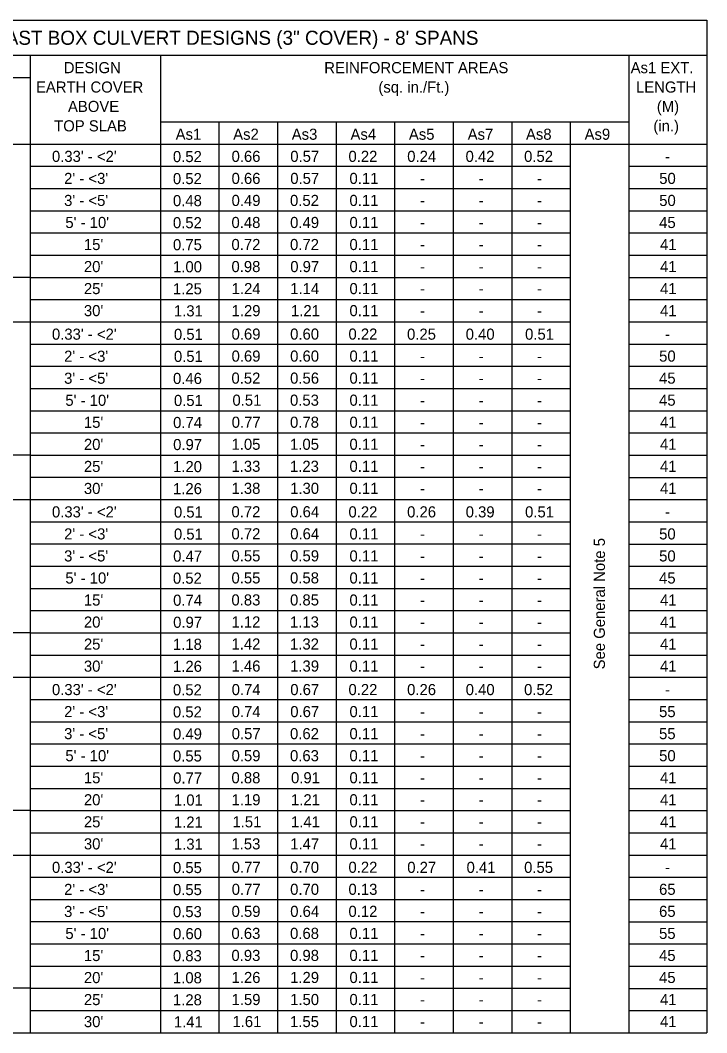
# Model space of a CAD drawing. Extents: x 10342.77 to 10344.98, y 76371.53 to 76372.62.
# Drawn here: x 10342.983 to 10343.372, y 76371.961 to 76372.535 of the extents above; entities that cross this region are included whole.
import ezdxf

# ---------------------------------------------------------------- set-up
doc = ezdxf.new("R2010")
doc.units = 0
doc.layers.add('AdhocPoint_dp', color=7, linetype='Continuous')
doc.layers.add('PlotBorder_dp', color=7, linetype='Continuous')

msp = doc.modelspace()

# ---------------------------------------------------------------- linework, layer by layer
at = {"layer": 'PlotBorder_dp'}
for p, q in [((10342.7771, 76372.53475), (10343.37184, 76372.53475)), ((10343.37184, 76372.53475), (10343.37184, 76371.96053)), ((10342.7771, 76372.51488), (10343.37184, 76372.51488)), ((10342.98818, 76372.51488), (10342.98818, 76371.96053)), ((10343.06206, 76372.51488), (10343.06206, 76371.96053)), ((10343.32765, 76372.51488), (10343.32765, 76371.96053)), ((10342.84574, 76372.50228), (10342.98818, 76372.50228)), ((10343.06206, 76372.47713), (10343.32765, 76372.47713)), ((10343.09526, 76372.47713), (10343.09526, 76371.96053)), ((10343.12846, 76372.47713), (10343.12846, 76371.96053)), ((10343.16166, 76372.47713), (10343.16166, 76371.96053)), ((10343.19486, 76372.47713), (10343.19486, 76371.96053)), ((10343.22806, 76372.47713), (10343.22806, 76371.96053)), ((10343.22806, 76372.47713), (10343.22806, 76371.96053)), ((10343.26125, 76372.47713), (10343.26125, 76371.96053)), ((10343.29445, 76372.47713), (10343.29445, 76371.96053)), ((10342.7771, 76372.46453), (10343.37184, 76372.46453)), ((10342.98818, 76372.45193), (10343.29445, 76372.45193)), ((10343.32765, 76372.45191), (10343.37184, 76372.45191)), ((10342.98818, 76372.43933), (10343.29445, 76372.43933)), ((10343.32765, 76372.43931), (10343.37184, 76372.43931)), ((10342.98818, 76372.42673), (10343.29445, 76372.42673)), ((10343.32765, 76372.42671), (10343.37184, 76372.42671)), ((10342.98818, 76372.41413), (10343.29445, 76372.41413)), ((10343.32765, 76372.41411), (10343.37184, 76372.41411)), ((10342.98818, 76372.40153), (10343.29445, 76372.40153)), ((10343.32765, 76372.40151), (10343.37184, 76372.40151)), ((10342.98818, 76372.38893), (10342.84574, 76372.38893)), ((10342.98818, 76372.38893), (10343.29445, 76372.38893)), ((10343.32765, 76372.38891), (10343.37184, 76372.38891)), ((10342.98818, 76372.37633), (10343.29445, 76372.37633)), ((10343.32765, 76372.37631), (10343.37184, 76372.37631)), ((10342.7771, 76372.36373), (10343.29445, 76372.36373)), ((10342.98281, 76372.36373), (10343.29445, 76372.36373)), ((10342.9888, 76372.36371), (10343.06097, 76372.36371)), ((10342.9888, 76372.36371), (10343.06097, 76372.36371)), ((10343.32765, 76372.36371), (10343.37184, 76372.36371)), ((10343.32765, 76372.36371), (10343.37184, 76372.36371)), ((10342.98818, 76372.35113), (10343.29445, 76372.35113)), ((10343.32765, 76372.35111), (10343.37184, 76372.35111)), ((10342.98818, 76372.33853), (10343.29445, 76372.33853)), ((10343.32765, 76372.33851), (10343.37184, 76372.33851)), ((10342.98818, 76372.32593), (10343.29445, 76372.32593)), ((10343.32765, 76372.32591), (10343.37184, 76372.32591)), ((10342.98818, 76372.31333), (10343.29445, 76372.31333)), ((10343.32765, 76372.31331), (10343.37184, 76372.31331)), ((10342.98818, 76372.30073), (10343.29445, 76372.30073)), ((10343.32765, 76372.30071), (10343.37184, 76372.30071)), ((10342.98818, 76372.28813), (10342.84574, 76372.28813)), ((10342.98818, 76372.28813), (10343.29445, 76372.28813)), ((10343.32765, 76372.28811), (10343.37184, 76372.28811)), ((10342.98818, 76372.27553), (10343.29445, 76372.27553)), ((10343.32765, 76372.27551), (10343.37184, 76372.27551)), ((10342.7771, 76372.26293), (10343.29445, 76372.26293)), ((10342.98281, 76372.26293), (10343.29445, 76372.26293)), ((10342.9888, 76372.26291), (10343.06097, 76372.26291)), ((10342.9888, 76372.26291), (10343.06097, 76372.26291)), ((10342.9888, 76372.26291), (10343.06097, 76372.26291)), ((10343.32765, 76372.26291), (10343.37184, 76372.26291)), ((10343.32765, 76372.26291), (10343.37184, 76372.26291)), ((10342.98818, 76372.25033), (10343.29445, 76372.25033)), ((10343.32765, 76372.25031), (10343.37184, 76372.25031)), ((10342.98818, 76372.23773), (10343.29445, 76372.23773)), ((10343.32765, 76372.23771), (10343.37184, 76372.23771)), ((10342.98818, 76372.22513), (10343.29445, 76372.22513)), ((10343.32765, 76372.22511), (10343.37184, 76372.22511)), ((10342.98818, 76372.21253), (10343.29445, 76372.21253)), ((10343.32765, 76372.21251), (10343.37184, 76372.21251)), ((10342.98818, 76372.19993), (10343.29445, 76372.19993)), ((10343.32765, 76372.19991), (10343.37184, 76372.19991)), ((10342.98818, 76372.18733), (10342.84574, 76372.18733)), ((10342.98818, 76372.18733), (10343.29445, 76372.18733)), ((10343.32765, 76372.18731), (10343.37184, 76372.18731)), ((10342.98818, 76372.17473), (10343.29445, 76372.17473)), ((10343.32765, 76372.17471), (10343.37184, 76372.17471)), ((10342.7771, 76372.16213), (10343.29445, 76372.16213)), ((10342.9888, 76372.16211), (10343.06097, 76372.16211)), ((10343.32765, 76372.16211), (10343.37184, 76372.16211)), ((10342.98818, 76372.14953), (10343.29445, 76372.14953)), ((10343.32765, 76372.14951), (10343.37184, 76372.14951)), ((10342.98818, 76372.13693), (10343.29445, 76372.13693)), ((10343.32765, 76372.13691), (10343.37184, 76372.13691)), ((10342.98818, 76372.12433), (10343.29445, 76372.12433)), ((10343.32765, 76372.12431), (10343.37184, 76372.12431)), ((10342.98818, 76372.11173), (10343.29445, 76372.11173)), ((10343.32765, 76372.11171), (10343.37184, 76372.11171)), ((10342.98818, 76372.09913), (10343.29445, 76372.09913)), ((10343.32765, 76372.09911), (10343.37184, 76372.09911)), ((10342.98818, 76372.08653), (10342.84574, 76372.08653)), ((10342.98818, 76372.08653), (10343.29445, 76372.08653)), ((10343.32765, 76372.08651), (10343.37184, 76372.08651)), ((10342.98818, 76372.07393), (10343.29445, 76372.07393)), ((10343.32765, 76372.07391), (10343.37184, 76372.07391)), ((10342.7771, 76372.06133), (10343.29445, 76372.06133)), ((10342.9888, 76372.06131), (10343.06097, 76372.06131)), ((10343.32765, 76372.06131), (10343.37184, 76372.06131)), ((10342.98818, 76372.04873), (10343.29445, 76372.04873)), ((10343.32765, 76372.04871), (10343.37184, 76372.04871)), ((10342.98818, 76372.03613), (10343.29445, 76372.03613)), ((10343.32765, 76372.03611), (10343.37184, 76372.03611)), ((10342.98818, 76372.02353), (10343.29445, 76372.02353)), ((10343.32765, 76372.02351), (10343.37184, 76372.02351)), ((10342.98818, 76372.01093), (10343.29445, 76372.01093)), ((10343.32765, 76372.01091), (10343.37184, 76372.01091)), ((10342.98818, 76371.99833), (10343.29445, 76371.99833)), ((10343.32765, 76371.99831), (10343.37184, 76371.99831)), ((10342.98818, 76371.98573), (10342.84574, 76371.98573)), ((10342.98818, 76371.98573), (10343.29445, 76371.98573)), ((10343.32765, 76371.98571), (10343.37184, 76371.98571)), ((10342.98818, 76371.97313), (10343.29445, 76371.97313)), ((10342.9888, 76371.97311), (10343.06097, 76371.97311)), ((10343.32765, 76371.97311), (10343.37184, 76371.97311)), ((10342.7771, 76371.96053), (10343.37184, 76371.96053))]:
    msp.add_line(p, q, dxfattribs=at)

# ---------------------------------------------------------------- texts
at = {"layer": 'AdhocPoint_dp'}
for s, height, p in [('TABLE 12A - STANDARD PRECAST BOX CULVERT DESIGNS (3" COVER) - 8\' SPANS', 0.008, (10342.81744, 76372.52081)), ('As1', 0.0063, (10343.07068, 76372.46696)), ('As2', 0.0063, (10343.10331, 76372.46696)), ('As3', 0.0063, (10343.13651, 76372.46696)), ('As4', 0.0063, (10343.16984, 76372.46696)), ('As5', 0.0063, (10343.20294, 76372.46696)), ('As7', 0.0063, (10343.23628, 76372.46696)), ('As8', 0.0063, (10343.26933, 76372.46696)), ('As9', 0.0063, (10343.30257, 76372.46696))]:
    msp.add_text(s, height=height, dxfattribs=at).set_placement(p)
msp.add_text('See General Note 5', height=0.0063, rotation=90, dxfattribs=at).set_placement((10343.3141, 76372.16662))
at = {"layer": 'PlotBorder_dp'}
for s, p in [('DESIGN', (10343.00728, 76372.50472)), ('REINFORCEMENT AREAS', (10343.15496, 76372.50472)), ('EARTH COVER', (10342.99149, 76372.49372)), ('(sq. in./Ft.)', (10343.18566, 76372.49372)), ('ABOVE', (10343.00963, 76372.48272)), ('TOP SLAB', (10343.0018, 76372.47172)), ("0.33' - <2'", (10343.00054, 76372.45441)), ('0.52', (10343.06914, 76372.4543)), ('0.66', (10343.1024, 76372.45441)), ('0.57', (10343.13568, 76372.45441)), ('0.22', (10343.16869, 76372.45441)), ('0.24', (10343.202, 76372.45441)), ('0.42', (10343.23508, 76372.45441)), ('0.52', (10343.26827, 76372.45441)), ('-', (10343.34816, 76372.45441)), ("2' - <3'", (10343.00744, 76372.44191)), ('0.52', (10343.06914, 76372.4418)), ('0.66', (10343.1024, 76372.44191)), ('0.57', (10343.13568, 76372.44191)), ('0.11', (10343.16926, 76372.44191)), ('-', (10343.20928, 76372.44191)), ('-', (10343.24249, 76372.44191)), ('-', (10343.27567, 76372.44191)), ('50', (10343.3449, 76372.44191)), ("3' - <5'", (10343.00744, 76372.42941)), ('0.48', (10343.06916, 76372.4293)), ('0.49', (10343.1024, 76372.42941)), ('0.52', (10343.13554, 76372.42941)), ('0.11', (10343.16926, 76372.42941)), ('50', (10343.3449, 76372.42941)), ('-', (10343.20928, 76372.42941)), ('-', (10343.24249, 76372.42941)), ('-', (10343.27567, 76372.42941)), ("5' - 10'", (10343.00815, 76372.41691)), ('0.52', (10343.06914, 76372.4168)), ('0.48', (10343.10235, 76372.41691)), ('0.49', (10343.1356, 76372.41691)), ('0.11', (10343.16926, 76372.41691)), ('45', (10343.34485, 76372.41691)), ('-', (10343.20928, 76372.41691)), ('-', (10343.24249, 76372.41691)), ('-', (10343.27567, 76372.41691)), ("15'", (10343.01867, 76372.40441)), ('0.75', (10343.06916, 76372.4043)), ('0.72', (10343.10234, 76372.40441)), ('0.72', (10343.13554, 76372.40441)), ('0.11', (10343.16926, 76372.40441)), ('41', (10343.34539, 76372.40441)), ('-', (10343.20928, 76372.40441)), ('-', (10343.24249, 76372.40441)), ('-', (10343.27567, 76372.40441)), ("20'", (10343.01867, 76372.39191)), ('1.00', (10343.06922, 76372.3918)), ('0.98', (10343.10235, 76372.39191)), ('0.97', (10343.13568, 76372.39191)), ('0.11', (10343.16926, 76372.39191)), ('41', (10343.34539, 76372.39191)), ('-', (10343.20928, 76372.39191)), ('-', (10343.24249, 76372.39191)), ('-', (10343.27567, 76372.39191)), ("25'", (10343.01867, 76372.37941)), ('1.25', (10343.06916, 76372.3793)), ('1.24', (10343.10246, 76372.37941)), ('1.14', (10343.13566, 76372.37941)), ('0.11', (10343.16926, 76372.37941)), ('-', (10343.20928, 76372.37941)), ('-', (10343.24249, 76372.37941)), ('-', (10343.27567, 76372.37941)), ('41', (10343.34539, 76372.37941)), ("30'", (10343.01867, 76372.36691)), ('1.31', (10343.06971, 76372.3668)), ('1.29', (10343.1024, 76372.36691)), ('1.21', (10343.13611, 76372.36691)), ('0.11', (10343.16926, 76372.36691)), ('-', (10343.20928, 76372.36691)), ('-', (10343.24249, 76372.36691)), ('-', (10343.27567, 76372.36691)), ('41', (10343.34539, 76372.36691)), ("0.33' - <2'", (10343.00054, 76372.35357)), ('0.51', (10343.06971, 76372.35347)), ('0.69', (10343.1024, 76372.35363)), ('0.60', (10343.13562, 76372.35363)), ('0.22', (10343.16869, 76372.35363)), ('0.25', (10343.2019, 76372.35357)), ('0.40', (10343.23516, 76372.35357)), ('0.51', (10343.26883, 76372.35357)), ('-', (10343.34811, 76372.35363)), ("2' - <3'", (10343.00744, 76372.34107)), ('0.51', (10343.06971, 76372.34097)), ('0.69', (10343.1024, 76372.34113)), ('0.60', (10343.13562, 76372.34113)), ('0.11', (10343.16926, 76372.34113)), ('50', (10343.34485, 76372.34113)), ('-', (10343.20928, 76372.34107)), ('-', (10343.24249, 76372.34107)), ('-', (10343.27567, 76372.34107)), ("3' - <5'", (10343.00744, 76372.32857)), ('0.46', (10343.0692, 76372.32847)), ('0.52', (10343.10234, 76372.32863)), ('0.56', (10343.1356, 76372.32863)), ('0.11', (10343.16926, 76372.32863)), ('45', (10343.3448, 76372.32863)), ('-', (10343.20928, 76372.32857)), ('-', (10343.24249, 76372.32857)), ('-', (10343.27567, 76372.32857)), ("5' - 10'", (10343.00815, 76372.31607)), ('0.51', (10343.06971, 76372.31597)), ('0.51', (10343.1029, 76372.31613)), ('0.53', (10343.13553, 76372.31613)), ('0.11', (10343.16926, 76372.31613)), ('-', (10343.20928, 76372.31607)), ('-', (10343.24249, 76372.31607)), ('-', (10343.27567, 76372.31607)), ('45', (10343.3448, 76372.31613)), ("15'", (10343.01867, 76372.30357)), ('0.74', (10343.06926, 76372.30347)), ('0.77', (10343.10248, 76372.30363)), ('0.78', (10343.13556, 76372.30363)), ('0.11', (10343.16926, 76372.30363)), ('-', (10343.20928, 76372.30357)), ('-', (10343.24249, 76372.30357)), ('-', (10343.27567, 76372.30357)), ('41', (10343.34534, 76372.30363)), ("20'", (10343.01867, 76372.29107)), ('0.97', (10343.06928, 76372.29097)), ('1.05', (10343.10236, 76372.29113)), ('1.05', (10343.13556, 76372.29113)), ('0.11', (10343.16926, 76372.29113)), ('41', (10343.34534, 76372.29113)), ('-', (10343.20928, 76372.29107)), ('-', (10343.24249, 76372.29107)), ('-', (10343.27567, 76372.29107)), ("25'", (10343.01867, 76372.27857)), ('1.20', (10343.06922, 76372.27847)), ('1.33', (10343.10233, 76372.27863)), ('1.23', (10343.13553, 76372.27863)), ('0.11', (10343.16926, 76372.27863)), ('41', (10343.34534, 76372.27863)), ('-', (10343.20928, 76372.27857)), ('-', (10343.24249, 76372.27857)), ('-', (10343.27567, 76372.27857)), ("30'", (10343.01867, 76372.26607)), ('1.26', (10343.0692, 76372.26597)), ('1.38', (10343.10235, 76372.26613)), ('1.30', (10343.13562, 76372.26613)), ('0.11', (10343.16926, 76372.26613)), ('41', (10343.34534, 76372.26613)), ('-', (10343.20928, 76372.26607)), ('-', (10343.24249, 76372.26607)), ('-', (10343.27567, 76372.26607)), ("0.33' - <2'", (10343.00054, 76372.25279)), ('0.51', (10343.06971, 76372.25269)), ('0.72', (10343.10234, 76372.25285)), ('0.64', (10343.13566, 76372.25285)), ('0.22', (10343.16869, 76372.25279)), ('0.26', (10343.20194, 76372.25279)), ('0.39', (10343.23515, 76372.25279)), ('0.51', (10343.26883, 76372.25279)), ('-', (10343.34811, 76372.25279)), ("2' - <3'", (10343.00744, 76372.24029)), ('0.51', (10343.06971, 76372.24019)), ('0.72', (10343.10234, 76372.24035)), ('0.64', (10343.13566, 76372.24035)), ('0.11', (10343.16926, 76372.24029)), ('-', (10343.20928, 76372.24029)), ('-', (10343.24249, 76372.24029)), ('-', (10343.27567, 76372.24029)), ('50', (10343.34485, 76372.24029)), ("3' - <5'", (10343.00744, 76372.22779)), ('0.47', (10343.06928, 76372.22769)), ('0.55', (10343.10236, 76372.22785)), ('0.59', (10343.1356, 76372.22785)), ('0.11', (10343.16926, 76372.22779)), ('50', (10343.34485, 76372.22779)), ('-', (10343.20928, 76372.22779)), ('-', (10343.24249, 76372.22779)), ('-', (10343.27567, 76372.22779)), ("5' - 10'", (10343.00815, 76372.21529)), ('0.52', (10343.06914, 76372.21519)), ('0.55', (10343.10236, 76372.21535)), ('0.58', (10343.13556, 76372.21535)), ('0.11', (10343.16926, 76372.21529)), ('45', (10343.3448, 76372.21529)), ('-', (10343.20928, 76372.21529)), ('-', (10343.24249, 76372.21529)), ('-', (10343.27567, 76372.21529)), ("15'", (10343.01867, 76372.20279)), ('0.74', (10343.06926, 76372.20269)), ('0.83', (10343.10233, 76372.20285)), ('0.85', (10343.13556, 76372.20285)), ('0.11', (10343.16926, 76372.20279)), ('41', (10343.34534, 76372.20279)), ('-', (10343.20928, 76372.20279)), ('-', (10343.24249, 76372.20279)), ('-', (10343.27567, 76372.20279)), ("20'", (10343.01867, 76372.19029)), ('0.97', (10343.06928, 76372.19019)), ('1.12', (10343.10234, 76372.19035)), ('1.13', (10343.13553, 76372.19035)), ('0.11', (10343.16926, 76372.19029)), ('-', (10343.20928, 76372.19029)), ('-', (10343.24249, 76372.19029)), ('-', (10343.27567, 76372.19029)), ('41', (10343.34534, 76372.19029)), ("25'", (10343.01867, 76372.17779)), ('1.18', (10343.06916, 76372.17769)), ('1.42', (10343.10234, 76372.17785)), ('1.32', (10343.13554, 76372.17785)), ('0.11', (10343.16926, 76372.17779)), ('-', (10343.20928, 76372.17779)), ('-', (10343.24249, 76372.17779)), ('-', (10343.27567, 76372.17779)), ('41', (10343.34534, 76372.17779)), ("30'", (10343.01867, 76372.16529)), ('1.26', (10343.0692, 76372.16519)), ('1.46', (10343.1024, 76372.16535)), ('1.39', (10343.1356, 76372.16535)), ('0.11', (10343.16926, 76372.16529)), ('41', (10343.34534, 76372.16529)), ('-', (10343.20928, 76372.16529)), ('-', (10343.24249, 76372.16529)), ('-', (10343.27567, 76372.16529)), ("0.33' - <2'", (10343.00054, 76372.15201)), ('0.52', (10343.06914, 76372.15186)), ('0.74', (10343.10246, 76372.15201)), ('0.67', (10343.13568, 76372.15201)), ('0.22', (10343.16869, 76372.15201)), ('0.26', (10343.20194, 76372.15201)), ('0.40', (10343.23516, 76372.15201)), ('0.52', (10343.26827, 76372.15201)), ('-', (10343.34811, 76372.15201)), ("2' - <3'", (10343.00744, 76372.13951)), ('0.52', (10343.06914, 76372.13936)), ('0.74', (10343.10246, 76372.13951)), ('0.67', (10343.13568, 76372.13951)), ('0.11', (10343.16926, 76372.13951)), ('55', (10343.3448, 76372.13951)), ('-', (10343.20928, 76372.13951)), ('-', (10343.24249, 76372.13951)), ('-', (10343.27567, 76372.13951)), ("3' - <5'", (10343.00744, 76372.12701)), ('0.49', (10343.0692, 76372.12686)), ('0.57', (10343.10248, 76372.12701)), ('0.62', (10343.13554, 76372.12701)), ('0.11', (10343.16926, 76372.12701)), ('-', (10343.20928, 76372.12701)), ('-', (10343.24249, 76372.12701)), ('-', (10343.27567, 76372.12701)), ('55', (10343.3448, 76372.12701)), ("5' - 10'", (10343.00815, 76372.11451)), ('0.55', (10343.06916, 76372.11436)), ('0.59', (10343.1024, 76372.11451)), ('0.63', (10343.13553, 76372.11451)), ('0.11', (10343.16926, 76372.11451)), ('-', (10343.20928, 76372.11451)), ('-', (10343.24249, 76372.11451)), ('-', (10343.27567, 76372.11451)), ('50', (10343.34485, 76372.11451)), ("15'", (10343.01867, 76372.10201)), ('0.77', (10343.06928, 76372.10186)), ('0.88', (10343.10235, 76372.10201)), ('0.91', (10343.13611, 76372.10201)), ('0.11', (10343.16926, 76372.10201)), ('41', (10343.34534, 76372.10201)), ('-', (10343.20928, 76372.10201)), ('-', (10343.24249, 76372.10201)), ('-', (10343.27567, 76372.10201)), ("20'", (10343.01867, 76372.08951)), ('1.01', (10343.06971, 76372.08936)), ('1.19', (10343.1024, 76372.08951)), ('1.21', (10343.13611, 76372.08951)), ('0.11', (10343.16926, 76372.08951)), ('41', (10343.34534, 76372.08951)), ('-', (10343.20928, 76372.08951)), ('-', (10343.24249, 76372.08951)), ('-', (10343.27567, 76372.08951)), ("25'", (10343.01867, 76372.07701)), ('1.21', (10343.06971, 76372.07686)), ('1.51', (10343.1029, 76372.07701)), ('1.41', (10343.13611, 76372.07701)), ('0.11', (10343.16926, 76372.07701)), ('41', (10343.34534, 76372.07701)), ('-', (10343.20928, 76372.07701)), ('-', (10343.24249, 76372.07701)), ('-', (10343.27567, 76372.07701)), ("30'", (10343.01867, 76372.06451)), ('1.31', (10343.06971, 76372.06436)), ('1.53', (10343.10233, 76372.06451)), ('1.47', (10343.13568, 76372.06451)), ('0.11', (10343.16926, 76372.06451)), ('41', (10343.34534, 76372.06451)), ('-', (10343.20928, 76372.06451)), ('-', (10343.24249, 76372.06451)), ('-', (10343.27567, 76372.06451)), ("0.33' - <2'", (10343.00054, 76372.05118)), ('0.55', (10343.06916, 76372.05107)), ('0.77', (10343.10248, 76372.05123)), ('0.70', (10343.13562, 76372.05123)), ('0.22', (10343.16869, 76372.05123)), ('0.27', (10343.20202, 76372.05118)), ('0.41', (10343.23565, 76372.05118)), ('0.55', (10343.26829, 76372.05118)), ('-', (10343.34811, 76372.05123)), ("2' - <3'", (10343.00744, 76372.03868)), ('0.55', (10343.06916, 76372.03857)), ('0.77', (10343.10248, 76372.03873)), ('0.70', (10343.13562, 76372.03873)), ('0.13', (10343.16869, 76372.03873)), ('65', (10343.3448, 76372.03873)), ('-', (10343.20928, 76372.03868)), ('-', (10343.24249, 76372.03868)), ('-', (10343.27567, 76372.03868)), ("3' - <5'", (10343.00744, 76372.02618)), ('0.53', (10343.06913, 76372.02607)), ('0.59', (10343.1024, 76372.02623)), ('0.64', (10343.13566, 76372.02623)), ('0.12', (10343.16869, 76372.02623)), ('65', (10343.3448, 76372.02623)), ('-', (10343.20928, 76372.02618)), ('-', (10343.24249, 76372.02618)), ('-', (10343.27567, 76372.02618)), ("5' - 10'", (10343.00815, 76372.01368)), ('0.60', (10343.06922, 76372.01357)), ('0.63', (10343.10233, 76372.01373)), ('0.68', (10343.13556, 76372.01373)), ('0.11', (10343.16926, 76372.01373)), ('55', (10343.3448, 76372.01373)), ('-', (10343.20928, 76372.01368)), ('-', (10343.24249, 76372.01368)), ('-', (10343.27567, 76372.01368)), ("15'", (10343.01867, 76372.00118)), ('0.83', (10343.06913, 76372.00107)), ('0.93', (10343.10233, 76372.00123)), ('0.98', (10343.13556, 76372.00123)), ('0.11', (10343.16926, 76372.00123)), ('45', (10343.3448, 76372.00123)), ('-', (10343.20928, 76372.00118)), ('-', (10343.24249, 76372.00118)), ('-', (10343.27567, 76372.00118)), ("20'", (10343.01867, 76371.98868)), ('1.08', (10343.06916, 76371.98857)), ('1.26', (10343.1024, 76371.98873)), ('1.29', (10343.1356, 76371.98873)), ('0.11', (10343.16926, 76371.98873)), ('-', (10343.20928, 76371.98868)), ('-', (10343.24249, 76371.98868)), ('-', (10343.27567, 76371.98868)), ('45', (10343.3448, 76371.98873)), ("25'", (10343.01867, 76371.97618)), ('1.28', (10343.06916, 76371.97607)), ('1.59', (10343.1024, 76371.97623)), ('1.50', (10343.13562, 76371.97623)), ('0.11', (10343.16926, 76371.97623)), ('-', (10343.20928, 76371.97618)), ('-', (10343.24249, 76371.97618)), ('-', (10343.27567, 76371.97618)), ('41', (10343.34534, 76371.97623)), ("30'", (10343.01867, 76371.96368)), ('1.41', (10343.06971, 76371.96357)), ('1.61', (10343.1029, 76371.96373)), ('1.55', (10343.13556, 76371.96373)), ('0.11', (10343.16926, 76371.96373)), ('41', (10343.34534, 76371.96373)), ('-', (10343.20928, 76371.96368)), ('-', (10343.24249, 76371.96368)), ('-', (10343.27567, 76371.96368))]:
    msp.add_text(s, height=0.0063, dxfattribs=at).set_placement(p)
for s, p in [('As1 EXT.', (10343.3287, 76372.50472)), ('LENGTH', (10343.33172, 76372.49372)), ('(M)', (10343.34353, 76372.48272)), ('(in.)', (10343.34157, 76372.47172))]:
    msp.add_text(s, height=0.0063, rotation=360, dxfattribs=at).set_placement(p)

doc.saveas('drawing.dxf')
